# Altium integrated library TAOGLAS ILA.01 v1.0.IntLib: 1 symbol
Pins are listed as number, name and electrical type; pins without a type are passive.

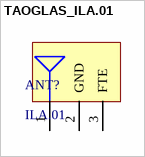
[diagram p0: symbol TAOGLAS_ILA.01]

## TAOGLAS_ILA.01
designator ANT?, comment ILA.01
915 MHz ISM Band Loop Antenna; ComponentLibStatus: Created; MFG: Taoglas; Temp_High: +85C; Temp_Low: -40C
footprint TAOGLAS_ILA.01 (915 MHz ISM Band Loop Antenna)
pins: 1 RF OUT, 2 GND, 3 FTE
